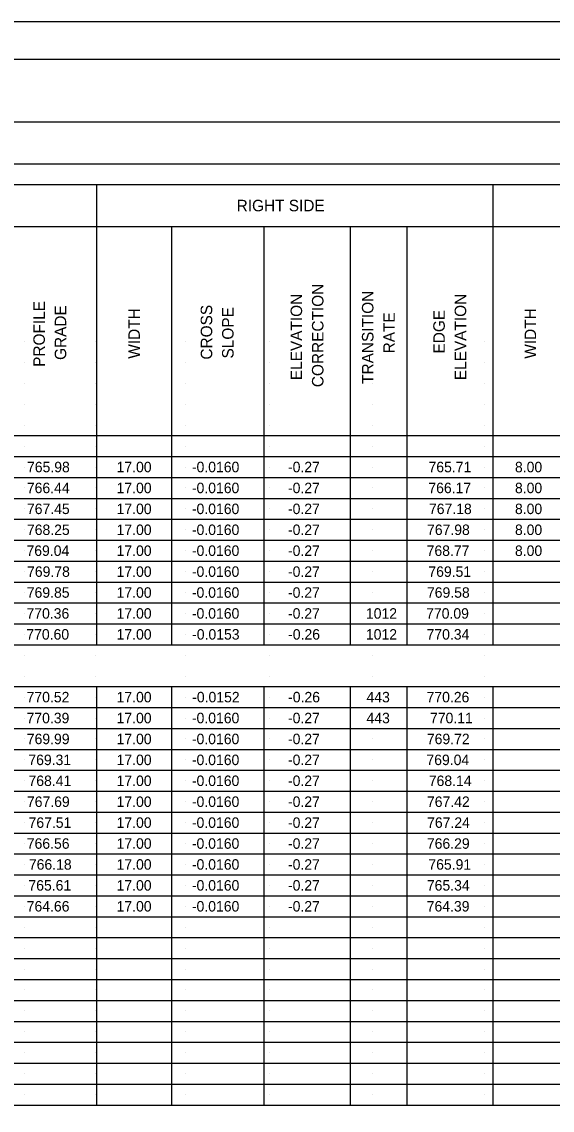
# Model space of a CAD drawing. Extents: x -15.4 to 18.6, y -12.6 to 9.4.
# Drawn here: x 3.72 to 10.82, y -5.18 to 9.39 of the extents above; entities that cross this region are included whole.
import ezdxf

# ---------------------------------------------------------------- set-up
doc = ezdxf.new("R2010")
doc.units = 0
for name, color, linetype in [('SH_Border', 7, 'Continuous'), ('SH_Cut_Line', 7, 'Continuous'), ('SH_Data', 7, 'Continuous'), ('SH_Text', 7, 'Continuous')]:
    doc.layers.add(name, color=color, linetype=linetype)

msp = doc.modelspace()

# ---------------------------------------------------------------- linework, layer by layer
at = {"layer": 'SH_Border'}
msp.add_lwpolyline([(-13.357, 8.888), (18.143, 8.888), (18.143, -12.112), (-13.357, -12.112)], close=True, dxfattribs=at)
at = {"layer": 'SH_Cut_Line'}
msp.add_lwpolyline([(-15.357, -12.612), (18.643, -12.612), (18.643, 9.388), (-15.357, 9.388)], close=True, dxfattribs=at)
at = {"layer": 'SH_Data'}
for p, q in [((-12.667, 8.888), (15.877, 8.888)), ((-11.514, 8.048), (13.999, 8.048)), ((-11.514, 7.488), (13.999, 7.488)), ((-12.667, 7.208), (15.877, 7.208)), ((4.726, 7.208), (4.726, 1.048)), ((10.03, 7.208), (10.03, 1.048)), ((-12.667, 6.648), (14.576, 6.648)), ((5.731, 6.648), (5.731, 1.048)), ((6.966, 6.648), (6.966, 1.048)), ((8.119, 6.648), (8.119, 1.048)), ((8.877, 6.648), (8.877, 1.048)), ((3.768, 5.108), (3.768, 5.108)), ((4.718, 5.108), (4.718, 5.108)), ((5.918, 5.108), (5.918, 5.108)), ((7.043, 5.108), (7.043, 5.108)), ((8.418, 5.108), (8.418, 5.108)), ((9.918, 5.108), (9.918, 5.108)), ((3.768, 4.828), (3.768, 4.828)), ((4.718, 4.828), (4.718, 4.828)), ((5.918, 4.828), (5.918, 4.828)), ((7.043, 4.828), (7.043, 4.828)), ((8.418, 4.828), (8.418, 4.828)), ((9.918, 4.828), (9.918, 4.828)), ((3.768, 4.548), (3.768, 4.548)), ((4.718, 4.548), (4.718, 4.548)), ((5.918, 4.548), (5.918, 4.548)), ((7.043, 4.548), (7.043, 4.548)), ((8.418, 4.548), (8.418, 4.548)), ((9.918, 4.548), (9.918, 4.548)), ((3.768, 4.268), (3.768, 4.268)), ((4.718, 4.268), (4.718, 4.268)), ((5.918, 4.268), (5.918, 4.268)), ((7.043, 4.268), (7.043, 4.268)), ((8.418, 4.268), (8.418, 4.268)), ((9.918, 4.268), (9.918, 4.268)), ((3.768, 3.988), (3.768, 3.988)), ((4.718, 3.988), (4.718, 3.988)), ((5.918, 3.988), (5.918, 3.988)), ((7.043, 3.988), (7.043, 3.988)), ((8.418, 3.988), (8.418, 3.988)), ((9.918, 3.988), (9.918, 3.988)), ((-12.667, 3.848), (15.877, 3.848)), ((3.768, 3.708), (3.768, 3.708)), ((4.718, 3.708), (4.718, 3.708)), ((5.918, 3.708), (5.918, 3.708)), ((7.043, 3.708), (7.043, 3.708)), ((8.418, 3.708), (8.418, 3.708)), ((9.918, 3.708), (9.918, 3.708)), ((-12.667, 3.568), (15.877, 3.568)), ((3.768, 3.428), (3.768, 3.428)), ((4.718, 3.428), (4.718, 3.428)), ((5.918, 3.428), (5.918, 3.428)), ((7.043, 3.428), (7.043, 3.428)), ((8.418, 3.428), (8.418, 3.428)), ((9.918, 3.428), (9.918, 3.428)), ((-12.667, 3.288), (15.877, 3.288)), ((3.768, 3.148), (3.768, 3.148)), ((4.718, 3.148), (4.718, 3.148)), ((5.918, 3.148), (5.918, 3.148)), ((7.043, 3.148), (7.043, 3.148)), ((8.418, 3.148), (8.418, 3.148)), ((9.918, 3.148), (9.918, 3.148)), ((-12.667, 3.008), (15.877, 3.008)), ((3.768, 2.868), (3.768, 2.868)), ((4.718, 2.868), (4.718, 2.868)), ((5.918, 2.868), (5.918, 2.868)), ((7.043, 2.868), (7.043, 2.868)), ((8.418, 2.868), (8.418, 2.868)), ((9.918, 2.868), (9.918, 2.868)), ((-12.667, 2.728), (15.877, 2.728)), ((3.768, 2.588), (3.768, 2.588)), ((4.718, 2.588), (4.718, 2.588)), ((5.918, 2.588), (5.918, 2.588)), ((7.043, 2.588), (7.043, 2.588)), ((8.418, 2.588), (8.418, 2.588)), ((9.918, 2.588), (9.918, 2.588)), ((-12.667, 2.448), (15.877, 2.448)), ((3.768, 2.308), (3.768, 2.308)), ((4.718, 2.308), (4.718, 2.308)), ((5.918, 2.308), (5.918, 2.308)), ((7.043, 2.308), (7.043, 2.308)), ((8.418, 2.308), (8.418, 2.308)), ((9.918, 2.308), (9.918, 2.308)), ((-12.667, 2.168), (15.877, 2.168)), ((3.768, 2.028), (3.768, 2.028)), ((4.718, 2.028), (4.718, 2.028)), ((5.918, 2.028), (5.918, 2.028)), ((7.043, 2.028), (7.043, 2.028)), ((8.418, 2.028), (8.418, 2.028)), ((9.918, 2.028), (9.918, 2.028)), ((-12.667, 1.888), (15.877, 1.888)), ((-12.667, 1.608), (15.877, 1.608)), ((3.768, 1.748), (3.768, 1.748)), ((4.718, 1.748), (4.718, 1.748)), ((5.918, 1.748), (5.918, 1.748)), ((7.043, 1.748), (7.043, 1.748)), ((8.418, 1.748), (8.418, 1.748)), ((9.918, 1.748), (9.918, 1.748)), ((3.768, 1.468), (3.768, 1.468)), ((4.718, 1.468), (4.718, 1.468)), ((5.918, 1.468), (5.918, 1.468)), ((7.043, 1.468), (7.043, 1.468)), ((8.418, 1.468), (8.418, 1.468)), ((9.918, 1.468), (9.918, 1.468)), ((-12.667, 1.328), (15.877, 1.328)), ((3.768, 1.188), (3.768, 1.188)), ((4.718, 1.188), (4.718, 1.188)), ((5.918, 1.188), (5.918, 1.188)), ((7.043, 1.188), (7.043, 1.188)), ((8.418, 1.188), (8.418, 1.188)), ((9.918, 1.188), (9.918, 1.188)), ((-12.667, 1.048), (15.877, 1.048)), ((3.768, 0.908), (3.768, 0.908)), ((4.718, 0.908), (4.718, 0.908)), ((5.918, 0.908), (5.918, 0.908)), ((7.043, 0.908), (7.043, 0.908)), ((8.418, 0.908), (8.418, 0.908)), ((9.918, 0.908), (9.918, 0.908)), ((3.768, 0.628), (3.768, 0.628)), ((4.718, 0.628), (4.718, 0.628)), ((5.918, 0.628), (5.918, 0.628)), ((7.043, 0.628), (7.043, 0.628)), ((8.418, 0.628), (8.418, 0.628)), ((9.918, 0.628), (9.918, 0.628)), ((-12.667, 0.488), (15.877, 0.488)), ((4.726, 0.488), (4.726, -5.112)), ((5.731, 0.488), (5.731, -5.112)), ((6.966, 0.488), (6.966, -5.112)), ((8.119, 0.488), (8.119, -5.112)), ((8.877, 0.488), (8.877, -5.112)), ((10.03, 0.488), (10.03, -5.112)), ((3.768, 0.348), (3.768, 0.348)), ((4.718, 0.348), (4.718, 0.348)), ((5.918, 0.348), (5.918, 0.348)), ((7.043, 0.348), (7.043, 0.348)), ((8.418, 0.348), (8.418, 0.348)), ((9.918, 0.348), (9.918, 0.348)), ((-12.667, 0.208), (15.877, 0.208)), ((3.768, 0.068), (3.768, 0.068)), ((4.718, 0.068), (4.718, 0.068)), ((5.918, 0.068), (5.918, 0.068)), ((7.043, 0.068), (7.043, 0.068)), ((8.418, 0.068), (8.418, 0.068)), ((9.918, 0.068), (9.918, 0.068)), ((-12.667, -0.072), (15.877, -0.072)), ((3.768, -0.212), (3.768, -0.212)), ((4.718, -0.212), (4.718, -0.212)), ((5.918, -0.212), (5.918, -0.212)), ((7.043, -0.212), (7.043, -0.212)), ((8.418, -0.212), (8.418, -0.212)), ((9.918, -0.212), (9.918, -0.212)), ((-12.667, -0.352), (15.877, -0.352)), ((3.768, -0.492), (3.768, -0.492)), ((4.718, -0.492), (4.718, -0.492)), ((5.918, -0.492), (5.918, -0.492)), ((7.043, -0.492), (7.043, -0.492)), ((8.418, -0.492), (8.418, -0.492)), ((9.918, -0.492), (9.918, -0.492)), ((-12.667, -0.632), (15.877, -0.632)), ((3.768, -0.772), (3.768, -0.772)), ((4.718, -0.772), (4.718, -0.772)), ((5.918, -0.772), (5.918, -0.772)), ((7.043, -0.772), (7.043, -0.772)), ((8.418, -0.772), (8.418, -0.772)), ((9.918, -0.772), (9.918, -0.772)), ((-12.667, -0.912), (15.877, -0.912)), ((3.768, -1.052), (3.768, -1.052)), ((4.718, -1.052), (4.718, -1.052)), ((5.918, -1.052), (5.918, -1.052)), ((7.043, -1.052), (7.043, -1.052)), ((8.418, -1.052), (8.418, -1.052)), ((9.918, -1.052), (9.918, -1.052)), ((-12.667, -1.192), (15.877, -1.192)), ((3.768, -1.332), (3.768, -1.332)), ((4.718, -1.332), (4.718, -1.332)), ((5.918, -1.332), (5.918, -1.332)), ((7.043, -1.332), (7.043, -1.332)), ((8.418, -1.332), (8.418, -1.332)), ((9.918, -1.332), (9.918, -1.332)), ((-12.667, -1.472), (15.877, -1.472)), ((3.768, -1.612), (3.768, -1.612)), ((4.718, -1.612), (4.718, -1.612)), ((5.918, -1.612), (5.918, -1.612)), ((7.043, -1.612), (7.043, -1.612)), ((8.418, -1.612), (8.418, -1.612)), ((9.918, -1.612), (9.918, -1.612)), ((-12.667, -1.752), (15.877, -1.752)), ((3.768, -1.892), (3.768, -1.892)), ((4.718, -1.892), (4.718, -1.892)), ((5.918, -1.892), (5.918, -1.892)), ((7.043, -1.892), (7.043, -1.892)), ((8.418, -1.892), (8.418, -1.892)), ((9.918, -1.892), (9.918, -1.892)), ((-12.667, -2.032), (15.877, -2.032)), ((3.768, -2.172), (3.768, -2.172)), ((4.718, -2.172), (4.718, -2.172)), ((5.918, -2.172), (5.918, -2.172)), ((7.043, -2.172), (7.043, -2.172)), ((8.418, -2.172), (8.418, -2.172)), ((9.918, -2.172), (9.918, -2.172)), ((-12.667, -2.312), (15.877, -2.312)), ((3.768, -2.452), (3.768, -2.452)), ((4.718, -2.452), (4.718, -2.452)), ((5.918, -2.452), (5.918, -2.452)), ((7.043, -2.452), (7.043, -2.452)), ((8.418, -2.452), (8.418, -2.452)), ((9.918, -2.452), (9.918, -2.452)), ((-12.667, -2.592), (15.877, -2.592)), ((3.768, -2.732), (3.768, -2.732)), ((4.718, -2.732), (4.718, -2.732)), ((5.918, -2.732), (5.918, -2.732)), ((7.043, -2.732), (7.043, -2.732)), ((8.418, -2.732), (8.418, -2.732)), ((9.918, -2.732), (9.918, -2.732)), ((-12.667, -2.872), (15.877, -2.872)), ((3.768, -3.012), (3.768, -3.012)), ((4.718, -3.012), (4.718, -3.012)), ((5.918, -3.012), (5.918, -3.012)), ((7.043, -3.012), (7.043, -3.012)), ((8.418, -3.012), (8.418, -3.012)), ((9.918, -3.012), (9.918, -3.012)), ((-12.667, -3.152), (15.877, -3.152)), ((3.768, -3.292), (3.768, -3.292)), ((4.718, -3.292), (4.718, -3.292)), ((5.918, -3.292), (5.918, -3.292)), ((7.043, -3.292), (7.043, -3.292)), ((8.418, -3.292), (8.418, -3.292)), ((9.918, -3.292), (9.918, -3.292)), ((-12.667, -3.432), (15.877, -3.432)), ((3.768, -3.572), (3.768, -3.572)), ((4.718, -3.572), (4.718, -3.572)), ((5.918, -3.572), (5.918, -3.572)), ((7.043, -3.572), (7.043, -3.572)), ((8.418, -3.572), (8.418, -3.572)), ((9.918, -3.572), (9.918, -3.572)), ((-12.667, -3.712), (15.877, -3.712)), ((3.768, -3.852), (3.768, -3.852)), ((4.718, -3.852), (4.718, -3.852)), ((5.918, -3.852), (5.918, -3.852)), ((7.043, -3.852), (7.043, -3.852)), ((8.418, -3.852), (8.418, -3.852)), ((9.918, -3.852), (9.918, -3.852)), ((-8.121, -3.992), (15.877, -3.992)), ((3.768, -4.132), (3.768, -4.132)), ((4.718, -4.132), (4.718, -4.132)), ((5.918, -4.132), (5.918, -4.132)), ((7.043, -4.132), (7.043, -4.132)), ((8.418, -4.132), (8.418, -4.132)), ((9.918, -4.132), (9.918, -4.132)), ((-8.121, -4.272), (15.877, -4.272)), ((3.768, -4.412), (3.768, -4.412)), ((4.718, -4.412), (4.718, -4.412)), ((5.918, -4.412), (5.918, -4.412)), ((7.043, -4.412), (7.043, -4.412)), ((8.418, -4.412), (8.418, -4.412)), ((9.918, -4.412), (9.918, -4.412)), ((-12.667, -4.552), (15.877, -4.552)), ((3.768, -4.692), (3.768, -4.692)), ((4.718, -4.692), (4.718, -4.692)), ((5.918, -4.692), (5.918, -4.692)), ((7.043, -4.692), (7.043, -4.692)), ((8.418, -4.692), (8.418, -4.692)), ((9.918, -4.692), (9.918, -4.692)), ((-12.667, -4.832), (15.877, -4.832)), ((3.768, -4.972), (3.768, -4.972)), ((4.718, -4.972), (4.718, -4.972)), ((5.918, -4.972), (5.918, -4.972)), ((7.043, -4.972), (7.043, -4.972)), ((8.418, -4.972), (8.418, -4.972)), ((9.918, -4.972), (9.918, -4.972)), ((-12.667, -5.112), (15.877, -5.112))]:
    msp.add_line(p, q, dxfattribs=at)

# ---------------------------------------------------------------- texts
at = {"layer": 'SH_Text'}
for s, height, p in [('RIGHT SIDE ', 0.154, (6.601, 6.851)), ('765.98', 0.14, (3.795, 3.358)), ('17.00', 0.14, (4.994, 3.358)), ('-0.0160', 0.14, (6.002, 3.358)), ('-0.27', 0.14, (7.288, 3.358)), ('765.71', 0.14, (9.169, 3.358)), ('8.00', 0.14, (10.326, 3.358)), ('766.44', 0.14, (3.793, 3.078)), ('17.00', 0.14, (4.994, 3.078)), ('-0.0160', 0.14, (6.002, 3.078)), ('-0.27', 0.14, (7.288, 3.078)), ('766.17', 0.14, (9.167, 3.078)), ('8.00', 0.14, (10.326, 3.078)), ('767.45', 0.14, (3.794, 2.798)), ('17.00', 0.14, (4.994, 2.798)), ('-0.0160', 0.14, (6.002, 2.798)), ('-0.27', 0.14, (7.288, 2.798)), ('767.18', 0.14, (9.175, 2.798)), ('8.00', 0.14, (10.326, 2.798)), ('768.25', 0.14, (3.794, 2.518)), ('17.00', 0.14, (4.994, 2.518)), ('-0.0160', 0.14, (6.002, 2.518)), ('-0.27', 0.14, (7.288, 2.518)), ('767.98', 0.14, (9.149, 2.518)), ('8.00', 0.14, (10.326, 2.518)), ('769.04', 0.14, (3.788, 2.238)), ('17.00', 0.14, (4.994, 2.238)), ('-0.0160', 0.14, (6.002, 2.238)), ('-0.27', 0.14, (7.288, 2.238)), ('768.77', 0.14, (9.144, 2.238)), ('8.00', 0.14, (10.326, 2.238)), ('769.78', 0.14, (3.796, 1.958)), ('17.00', 0.14, (4.994, 1.958)), ('-0.0160', 0.14, (6.002, 1.958)), ('-0.27', 0.14, (7.288, 1.958)), ('769.51', 0.14, (9.167, 1.958)), ('769.85', 0.14, (3.792, 1.678)), ('17.00', 0.14, (4.994, 1.678)), ('-0.0160', 0.14, (6.002, 1.678)), ('-0.27', 0.14, (7.288, 1.678)), ('769.58', 0.14, (9.148, 1.678)), ('770.36', 0.14, (3.788, 1.398)), ('17.00', 0.14, (4.994, 1.398)), ('-0.0160', 0.14, (6.002, 1.398)), ('-0.27', 0.14, (7.288, 1.398)), ('1012', 0.14, (8.331, 1.398)), ('770.09', 0.14, (9.137, 1.398)), ('770.60', 0.14, (3.786, 1.118)), ('17.00', 0.14, (4.994, 1.118)), ('-0.0153', 0.14, (6.005, 1.118)), ('-0.26', 0.14, (7.29, 1.118)), ('1012', 0.14, (8.331, 1.118)), ('770.34', 0.14, (9.143, 1.118)), ('770.52', 0.14, (3.79, 0.278)), ('17.00', 0.14, (4.994, 0.278)), ('-0.0152', 0.14, (6.006, 0.278)), ('-0.26', 0.14, (7.29, 0.278)), ('443', 0.14, (8.339, 0.278)), ('770.26', 0.14, (9.143, 0.278)), ('770.39', 0.14, (3.789, -0.002)), ('17.00', 0.14, (4.994, -0.002)), ('-0.0160', 0.14, (6.002, -0.002)), ('-0.27', 0.14, (7.288, -0.002)), ('443', 0.14, (8.339, -0.002)), ('770.11', 0.14, (9.189, -0.002)), ('769.99', 0.14, (3.792, -0.282)), ('17.00', 0.14, (4.994, -0.282)), ('-0.0160', 0.14, (6.002, -0.282)), ('-0.27', 0.14, (7.288, -0.282)), ('769.72', 0.14, (9.147, -0.282)), ('769.31', 0.14, (3.813, -0.562)), ('17.00', 0.14, (4.994, -0.562)), ('-0.0160', 0.14, (6.002, -0.562)), ('-0.27', 0.14, (7.288, -0.562)), ('769.04', 0.14, (9.141, -0.562)), ('768.41', 0.14, (3.815, -0.842)), ('17.00', 0.14, (4.994, -0.842)), ('-0.0160', 0.14, (6.002, -0.842)), ('-0.27', 0.14, (7.288, -0.842)), ('768.14', 0.14, (9.173, -0.842)), ('767.69', 0.14, (3.794, -1.122)), ('17.00', 0.14, (4.994, -1.122)), ('-0.0160', 0.14, (6.002, -1.122)), ('-0.27', 0.14, (7.288, -1.122)), ('767.42', 0.14, (9.148, -1.122)), ('767.51', 0.14, (3.816, -1.402)), ('17.00', 0.14, (4.994, -1.402)), ('-0.0160', 0.14, (6.002, -1.402)), ('-0.27', 0.14, (7.288, -1.402)), ('767.24', 0.14, (9.15, -1.402)), ('766.56', 0.14, (3.792, -1.682)), ('17.00', 0.14, (4.994, -1.682)), ('-0.0160', 0.14, (6.002, -1.682)), ('-0.27', 0.14, (7.288, -1.682)), ('766.29', 0.14, (9.147, -1.682)), ('766.18', 0.14, (3.82, -1.962)), ('17.00', 0.14, (4.994, -1.962)), ('-0.0160', 0.14, (6.002, -1.962)), ('-0.27', 0.14, (7.288, -1.962)), ('765.91', 0.14, (9.167, -1.962)), ('765.61', 0.14, (3.814, -2.242)), ('17.00', 0.14, (4.994, -2.242)), ('-0.0160', 0.14, (6.002, -2.242)), ('-0.27', 0.14, (7.288, -2.242)), ('765.34', 0.14, (9.147, -2.242)), ('764.66', 0.14, (3.791, -2.522)), ('17.00', 0.14, (4.994, -2.522)), ('-0.0160', 0.14, (6.002, -2.522)), ('-0.27', 0.14, (7.288, -2.522)), ('764.39', 0.14, (9.145, -2.522))]:
    msp.add_text(s, height=height, dxfattribs=at).set_placement(p)
for s, p in [('CORRECTION', (7.763, 4.497)), ('ELEVATION', (7.477, 4.591)), ('TRANSITION', (8.432, 4.541)), ('ELEVATION', (9.673, 4.591)), ('PROFILE', (4.034, 4.769)), ('GRADE', (4.32, 4.861)), ('CROSS', (6.274, 4.866)), ('SLOPE', (6.56, 4.881)), ('WIDTH', (5.306, 4.878)), ('RATE', (8.718, 4.95)), ('EDGE', (9.387, 4.948)), ('WIDTH', (10.609, 4.878))]:
    msp.add_text(s, height=0.154, rotation=90, dxfattribs=at).set_placement(p)

doc.saveas('drawing.dxf')
